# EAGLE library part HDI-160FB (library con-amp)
AMP connector
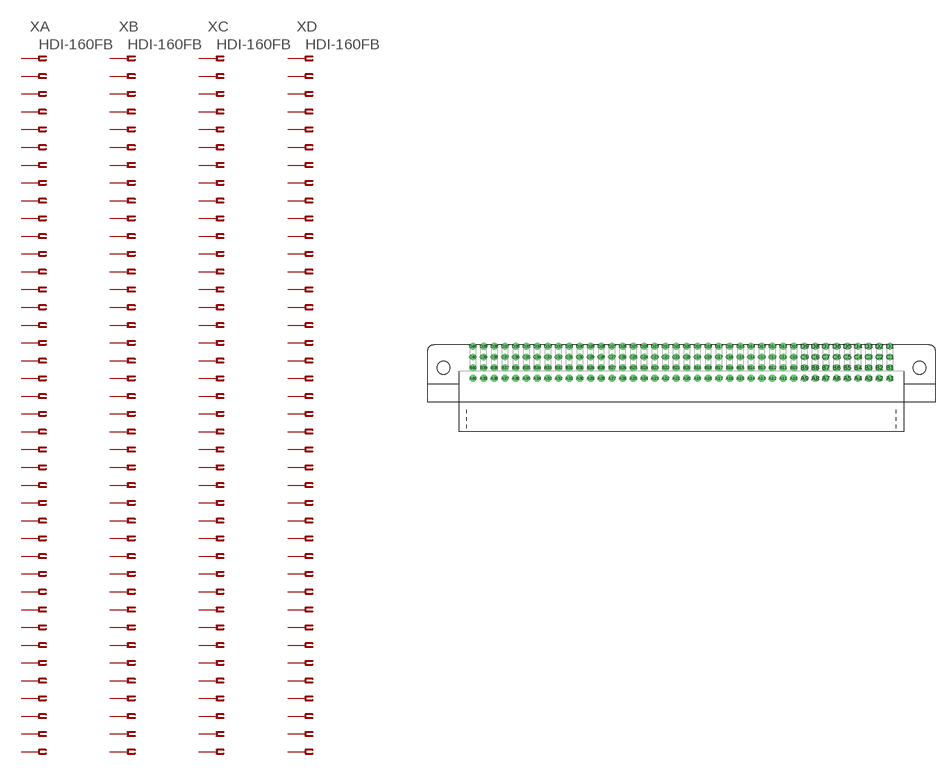
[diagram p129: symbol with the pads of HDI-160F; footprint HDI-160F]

Designator prefix X; gates A=PIN40F B=PIN40F C=PIN40F D=PIN40F

## HDI-160FB (MPN: 5532434-5; OC_FARNELL: unknown; OC_NEWARK: 19R2415)  [HDI-160F]
A1  A:1  pas
A2  A:2  pas
A3  A:3  pas
A4  A:4  pas
A5  A:5  pas
A6  A:6  pas
A7  A:7  pas
A8  A:8  pas
A9  A:9  pas
A10  A:10  pas
A11  A:11  pas
A12  A:12  pas
A13  A:13  pas
A14  A:14  pas
A15  A:15  pas
A16  A:16  pas
A17  A:17  pas
A18  A:18  pas
A19  A:19  pas
A20  A:20  pas
A21  A:21  pas
A22  A:22  pas
A23  A:23  pas
A24  A:24  pas
A25  A:25  pas
A26  A:26  pas
A27  A:27  pas
A28  A:28  pas
A29  A:29  pas
A30  A:30  pas
A31  A:31  pas
A32  A:32  pas
A33  A:33  pas
A34  A:34  pas
A35  A:35  pas
A36  A:36  pas
A37  A:37  pas
A38  A:38  pas
A39  A:39  pas
A40  A:40  pas
B1  B:1  pas
B2  B:2  pas
B3  B:3  pas
B4  B:4  pas
B5  B:5  pas
B6  B:6  pas
B7  B:7  pas
B8  B:8  pas
B9  B:9  pas
B10  B:10  pas
B11  B:11  pas
B12  B:12  pas
B13  B:13  pas
B14  B:14  pas
B15  B:15  pas
B16  B:16  pas
B17  B:17  pas
B18  B:18  pas
B19  B:19  pas
B20  B:20  pas
B21  B:21  pas
B22  B:22  pas
B23  B:23  pas
B24  B:24  pas
B25  B:25  pas
B26  B:26  pas
B27  B:27  pas
B28  B:28  pas
B29  B:29  pas
B30  B:30  pas
B31  B:31  pas
B32  B:32  pas
B33  B:33  pas
B34  B:34  pas
B35  B:35  pas
B36  B:36  pas
B37  B:37  pas
B38  B:38  pas
B39  B:39  pas
B40  B:40  pas
C1  C:1  pas
C2  C:2  pas
C3  C:3  pas
C4  C:4  pas
C5  C:5  pas
C6  C:6  pas
C7  C:7  pas
C8  C:8  pas
C9  C:9  pas
C10  C:10  pas
C11  C:11  pas
C12  C:12  pas
C13  C:13  pas
C14  C:14  pas
C15  C:15  pas
C16  C:16  pas
C17  C:17  pas
C18  C:18  pas
C19  C:19  pas
C20  C:20  pas
C21  C:21  pas
C22  C:22  pas
C23  C:23  pas
C24  C:24  pas
C25  C:25  pas
C26  C:26  pas
C27  C:27  pas
C28  C:28  pas
C29  C:29  pas
C30  C:30  pas
C31  C:31  pas
C32  C:32  pas
C33  C:33  pas
C34  C:34  pas
C35  C:35  pas
C36  C:36  pas
C37  C:37  pas
C38  C:38  pas
C39  C:39  pas
C40  C:40  pas
D1  D:1  pas
D2  D:2  pas
D3  D:3  pas
D4  D:4  pas
D5  D:5  pas
D6  D:6  pas
D7  D:7  pas
D8  D:8  pas
D9  D:9  pas
D10  D:10  pas
D11  D:11  pas
D12  D:12  pas
D13  D:13  pas
D14  D:14  pas
D15  D:15  pas
D16  D:16  pas
D17  D:17  pas
D18  D:18  pas
D19  D:19  pas
D20  D:20  pas
D21  D:21  pas
D22  D:22  pas
D23  D:23  pas
D24  D:24  pas
D25  D:25  pas
D26  D:26  pas
D27  D:27  pas
D28  D:28  pas
D29  D:29  pas
D30  D:30  pas
D31  D:31  pas
D32  D:32  pas
D33  D:33  pas
D34  D:34  pas
D35  D:35  pas
D36  D:36  pas
D37  D:37  pas
D38  D:38  pas
D39  D:39  pas
D40  D:40  pas

## Footprint HDI-160F (pad centres in mm)
AMP connector
drill 1.09 octagon: A1 49.53,-2.54; A2 46.99,-2.54; A3 44.45,-2.54; A4 41.91,-2.54; A5 39.37,-2.54; A6 36.83,-2.54; A7 34.29,-2.54; A8 31.75,-2.54; A9 29.21,-2.54; A10 26.67,-2.54; A11 24.13,-2.54; A12 21.59,-2.54; A13 19.05,-2.54; A14 16.51,-2.54; A15 13.97,-2.54; A16 11.43,-2.54; A17 8.89,-2.54; A18 6.35,-2.54; A19 3.81,-2.54; A20 1.27,-2.54; A21 -1.27,-2.54; A22 -3.81,-2.54; A23 -6.35,-2.54; A24 -8.89,-2.54; A25 -11.43,-2.54; A26 -13.97,-2.54; A27 -16.51,-2.54; A28 -19.05,-2.54; A29 -21.59,-2.54; A30 -24.13,-2.54; A31 -26.67,-2.54; A32 -29.21,-2.54; A33 -31.75,-2.54; A34 -34.29,-2.54; A35 -36.83,-2.54; A36 -39.37,-2.54; A37 -41.91,-2.54; A38 -44.45,-2.54; A39 -46.99,-2.54; A40 -49.53,-2.54
drill 1.09 round: B1 49.53,0; B2 46.99,0; B3 44.45,0; B4 41.91,0; B5 39.37,0; B6 36.83,0; B7 34.29,0; B8 31.75,0; B9 29.21,0; B10 26.67,0; B11 24.13,0; B12 21.59,0; B13 19.05,0; B14 16.51,0; B15 13.97,0; B16 11.43,0; B17 8.89,0; B18 6.35,0; B19 3.81,0; B20 1.27,0; B21 -1.27,0; B22 -3.81,0; B23 -6.35,0; B24 -8.89,0; B25 -11.43,0; B26 -13.97,0; B27 -16.51,0; B28 -19.05,0; B29 -21.59,0; B30 -24.13,0; B31 -26.67,0; B32 -29.21,0; B33 -31.75,0; B34 -34.29,0; B35 -36.83,0; B36 -39.37,0; B37 -41.91,0; B38 -44.45,0; B39 -46.99,0; B40 -49.53,0; C1 49.53,2.54; C2 46.99,2.54; C3 44.45,2.54; C4 41.91,2.54; C5 39.37,2.54; C6 36.83,2.54; C7 34.29,2.54; C8 31.75,2.54; C9 29.21,2.54; C10 26.67,2.54; C11 24.13,2.54; C12 21.59,2.54; C13 19.05,2.54; C14 16.51,2.54; C15 13.97,2.54; C16 11.43,2.54; C17 8.89,2.54; C18 6.35,2.54; C19 3.81,2.54; C20 1.27,2.54; C21 -1.27,2.54; C22 -3.81,2.54; C23 -6.35,2.54; C24 -8.89,2.54; C25 -11.43,2.54; C26 -13.97,2.54; C27 -16.51,2.54; C28 -19.05,2.54; C29 -21.59,2.54; C30 -24.13,2.54; C31 -26.67,2.54; C32 -29.21,2.54; C33 -31.75,2.54; C34 -34.29,2.54; C35 -36.83,2.54; C36 -39.37,2.54; C37 -41.91,2.54; C38 -44.45,2.54; C39 -46.99,2.54; C40 -49.53,2.54; D1 49.53,5.08; D2 46.99,5.08; D3 44.45,5.08; D4 41.91,5.08; D5 39.37,5.08; D6 36.83,5.08; D7 34.29,5.08; D8 31.75,5.08; D9 29.21,5.08; D10 26.67,5.08; D11 24.13,5.08; D12 21.59,5.08; D13 19.05,5.08; D14 16.51,5.08; D15 13.97,5.08; D16 11.43,5.08; D17 8.89,5.08; D18 6.35,5.08; D19 3.81,5.08; D20 1.27,5.08; D21 -1.27,5.08; D22 -3.81,5.08; D23 -6.35,5.08; D24 -8.89,5.08; D25 -11.43,5.08; D26 -13.97,5.08; D27 -16.51,5.08; D28 -19.05,5.08; D29 -21.59,5.08; D30 -24.13,5.08; D31 -26.67,5.08; D32 -29.21,5.08; D33 -31.75,5.08; D34 -34.29,5.08; D35 -36.83,5.08; D36 -39.37,5.08; D37 -41.91,5.08; D38 -44.45,5.08; D39 -46.99,5.08; D40 -49.53,5.08
hole 3.05 at -56.51,0
hole 3.05 at 56.51,0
